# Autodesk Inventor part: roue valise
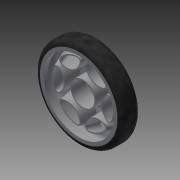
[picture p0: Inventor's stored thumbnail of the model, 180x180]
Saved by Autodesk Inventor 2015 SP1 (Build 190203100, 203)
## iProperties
Created: 2014-11
Part Number: roue valise
Material: Générique
Document SubType Name: Modeling
Designer: Dominique
Density: 1 g/cm^3
Appearance: Par défaut
Author: Dominique
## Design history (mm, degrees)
sketch "Esquisse1"
  geometry: L1 (0, 0)-(42, 0); L2 (42, 0)-(42, 16.5); L3 (42, 16.5)-(0, 16.5); L4 (0, 0)-(0, 21.5); L5 (0, 21.5)-(16, 21.5); L6 (16, 21.5)-(42, 16.5)
  constraints: 12 end point, 4 perpendicular, 1 horizontal
  dimensions: "d0" = 42 distance of L1.start L1.end; "d1" = 16.5 distance of L1.end L2.end; "d2" = 90 deg angle of L2 L1 (derived); "d3" = 21.5 distance of L1.start L4.end; "d4" = 16 distance of L4.end L5.end
revolve "Révolution1" sketch "Esquisse1" stored, may be unused: angle "d5" = 90 deg
fillet "Congé1" dims "d6" = 5
fillet "Congé2" dims "d7" = 5
sketch "Esquisse2"
  geometry: C1 r 15 at (0, 0); 1 further point
  constraints: 1 centre point, 1 coincident
  dimensions: "d8" = 30 diameter of C1
extrude "Extrusion1" cut sketch "Esquisse2" distance "d9" = 4; taper "d10" = 0 deg
sketch "Esquisse3"
  geometry: C1 r 11 at (0, 0); 1 further point
  constraints: 1 centre point, 1 coincident
  dimensions: "d11" = 22 diameter of C1
extrude "Extrusion2" cut sketch "Esquisse3" stored distance "d12" = 4; taper "d13" = 0 deg
sketch "Esquisse4"
  geometry: C1 r 18.25 at (0, 0); C2 r 27 at (0, 0); A1 r 12.5 centre (-30.75, 0) between (-21.97, -8.898) and (-21.97, 8.898); A2 r 20 centre (-7, 0) between (-25.194, 8.304) and (-25.194, -8.304); A3 r 2 centre (-23.375, -7.474) between (-25.194, -8.304) and (-21.97, -8.898); A4 r 2 centre (-23.375, 7.474) between (-21.97, 8.898) and (-25.194, 8.304); 1 further point
  constraints: 8 point on circle, 6 centre point, 5 tangent, 2 coincident, 1 equal radius
  dimensions: "d14" = 36.5 diameter of C1; "d15" = 54 diameter of C2; "d16" = 25 diameter of A1; "d18" = 2 radius of A3
extrude "Extrusion3" cut sketch "Esquisse4" stored distance "d19" = 4; taper "d20" = 0 deg
sketch "Esquisse6"
  geometry: L1 (-21.97, -8.898)-(-25.578, -12.458); L2 (-21.97, 8.898)-(-25.59, 12.47); A1 r 29.166 centre (-6.631, 0.021) between (-33.751, 10.75) and (-33.737, -10.744); A2 r 12.5 centre (-30.75, 0) between (-21.97, -8.898) and (-21.97, 8.898) reference; A3 r 2 centre (-23.375, 7.474) between (-21.97, 8.898) and (-25.194, 8.304) reference; A4 r 5 centre (-29.09, -8.899) between (-33.737, -10.744) and (-25.578, -12.458); A5 r 5 centre (-29.102, 8.911) between (-25.59, 12.47) and (-33.751, 10.75); 4 further points
  constraints: 9 point on circle, 6 tangent, 4 end point, 3 centre point, 2 point on line, 1 equal radius, 1 vertical alignment
  dimensions: "d23" = 5 radius of A4
sketch "Esquisse7"
  geometry: A1 r 12.5 centre (-30.75, 0) between (-21.97, -8.898) and (-21.97, 8.898) reference; A2 r 2 centre (-23.375, -7.474) between (-25.194, -8.304) and (-21.97, -8.898) reference; A3 r 20 centre (-7, 0) between (-25.194, 8.304) and (-25.194, -8.304) reference; A4 r 2 centre (-23.375, 7.474) between (-21.97, 8.898) and (-25.194, 8.304) reference; 1 further point
feature "Lissage1" dims "d24" = 0, "d25" = 90 deg, "d26" = 0, "d27" = 90 deg
  node "Arêtes1"
pattern_circular "Réseau circulaire1" dims angle "d29" = 360 deg
sketch "Esquisse8"
  geometry: C1 r 33.627 at (0, 0); 1 further point
  constraints: 1 centre point, 1 coincident
extrude "Extrusion5" cut sketch "Esquisse8" distance "d31" = 4; taper "d32" = 0 deg
feature "Coque1" dims "d33" = 1
node "Solide1"
